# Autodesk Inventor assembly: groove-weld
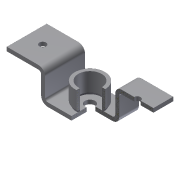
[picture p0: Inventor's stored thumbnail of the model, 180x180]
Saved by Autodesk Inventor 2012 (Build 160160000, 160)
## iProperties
Created: 2005-03
Part Number: groove-weld
Document SubType Name: Weldment
Designer: CADCIM
Manufacturer: Standard
Standards Organization: Custom
Author: CADCIM
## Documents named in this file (3)
- C:\Users\CadCim\Documents\SAILESH\inventor-2011-fact-prt\c16-inv-2011-prt\c16_inv_2012_prt\fig 16-16\groove-weld.iam
- C:\Users\CadCim\Documents\SAILESH\inventor-2011-fact-prt\c16-inv-2011-prt\fig-16-16\Bracket.ipt
- C:\Users\CadCim\Documents\SAILESH\inventor-2011-fact-prt\c16-inv-2011-prt\fig-16-16\cylinder.ipt
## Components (2 placed, 2 different names)
1. Bracket:1 — Insert:1
2. cylinder:1 — Insert:1
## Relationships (1: Insert 1)
- Insert:1: Bracket:1 ↔ cylinder:1
